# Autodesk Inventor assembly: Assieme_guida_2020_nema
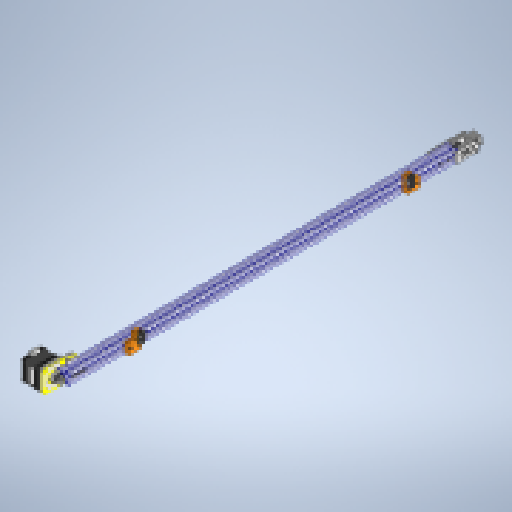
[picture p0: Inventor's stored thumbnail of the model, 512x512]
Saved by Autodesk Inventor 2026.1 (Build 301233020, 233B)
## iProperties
Created: 2026-01
Part Number: Assieme_guida_2020_nema
Document SubType Name: Assembly
Designer: hp
Sending System: Autodesk Inventor 2025
Preprocessor: ST-DEVELOPER v20
Title: Assieme_guida_2020_nema.stp
Author: R5800u
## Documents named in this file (16)
- C:\Users\hp\Documents\Inventor\DOM1_CartesianRobot\Assieme_guida_2020_nema - Copy.iam
- C:\Users\hp\Documents\Inventor\DOM1_CartesianRobot\2020 Belt Tensioner G_K.iam
- C:\Users\hp\Documents\Inventor\DOM1_CartesianRobot\GT2_20T.ipt
- C:\Users\hp\Documents\Inventor\DOM1_CartesianRobot\NO-NC Limit Switch.ipt
- C:\Users\hp\Documents\Inventor\DOM1_CartesianRobot\blocco_sensore.ipt
- C:\Users\hp\Documents\Inventor\DOM1_CartesianRobot\blocco_sensore_MIR.ipt
- C:\Users\hp\Documents\Inventor\DOM1_CartesianRobot\NEMA 42SHDC3030Z.ipt
- C:\Users\hp\Documents\Inventor\DOM1_CartesianRobot\blocco_nema.ipt
- C:\Users\hp\Documents\Inventor\DOM1_CartesianRobot\2020v2.ipt
- C:\Users\hp\Documents\Inventor\Content Center Files\R2026\en-US\ISO 4762(2)\ISO 4762 - M4 x 25ISO.ipt
- C:\Users\hp\Documents\Inventor\Content Center Files\R2026\en-US\ISO 4762(2)\ISO 4762 - M3 x 25ISO.ipt
- C:\Users\hp\Documents\Inventor\Content Center Files\R2021\en-US\ISO 4017(1)\ISO 4017 - M2 x 8 - ISO.ipt
- C:\Users\hp\Documents\Inventor\Content Center Files\R2026\en-US\ISO 4017(1)\ISO 4017 - M4 x 25 - ISO.ipt
- C:\Users\hp\Documents\Inventor\DOM1_CartesianRobot\2020 M4 (1).ipt
- C:\Users\hp\Documents\Inventor\Content Center Files\R2026\en-US\ANSI B18.3.1M(5)\ANSI B18.3.1M - M3x0.5 x 45(3).ipt
- C:\Users\hp\Documents\Inventor\Content Center Files\R2026\en-US\ISO 4032(2)\ISO 4032 - M3 - ISO.ipt
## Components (27 placed, 15 different names)
1. 2020:1
2. 2020 Belt Tensioner G_K:1 [sub-assembly]
3. GT2_20T:1 — Rigid:1
4. NO-NC Limit Switch:1 — Mate:9, Mate:10, Mate:11, Mate:36, Mate:37, Mate:38, Mate:39
5. NO-NC Limit Switch:2 — Mate:17, Mate:18, Mate:19
6. blocco_sensore:1
7. blocco_sensore_MIR:1 — Mate:15, Mate:16, Mate:17, Mate:18, Mate:19
8. NEMA 42SHDC3030Z:1
9. blocco_nema:1
10. ISO 4762 M3 x 25:1 — Mate:32, Mate:33
11. ISO 4762 M3 x 25:2 — Mate:34, Mate:35
12. ISO 4017 M2 x 8:1 — Mate:36, Mate:37
13. ISO 4017 M2 x 8:2 — Mate:38, Mate:39
14. ISO 4017 M4 x 25:1 — Mate:40, Mate:41
15. ISO 4017 M4 x 25:2 — Mate:42, Mate:43
16. 2020 M4 (1):1 — Mate:44, Angle:1, Mate:51
17. 2020 M4 (1):2 — Mate:45, Angle:2, Mate:50
18. ISO 4762 M4 x 25:1 — Mate:46, Mate:47, Mate:50
19. ISO 4762 M4 x 25:2 — Mate:48, Mate:49, Mate:51
20. Drilled Forged Hexagon Socket Head Cap Screw - 6 Holes - Metric M3x0.5 x 45:1 — Mate:52, Mate:53
21. ISO 4032 M3:1 — Mate:60, Mate:61
22. Drilled Forged Hexagon Socket Head Cap Screw - 6 Holes - Metric M3x0.5 x 45:2 — Mate:54, Mate:55
23. Drilled Forged Hexagon Socket Head Cap Screw - 6 Holes - Metric M3x0.5 x 45:3 — Mate:56, Mate:57
24. Drilled Forged Hexagon Socket Head Cap Screw - 6 Holes - Metric M3x0.5 x 45:4 — Mate:58, Mate:59
25. ISO 4032 M3:2 — Mate:62, Mate:63
26. ISO 4032 M3:3 — Mate:64, Mate:65
27. ISO 4032 M3:4 — Mate:66, Mate:67
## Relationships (47: Mate 44, Angle 2, WeldJoint 1)
- Rigid:1 [WeldJoint]: GT2_20T:1
- Mate:9: NO-NC Limit Switch:1
- Mate:10: NO-NC Limit Switch:1
- Mate:11: NO-NC Limit Switch:1
- Mate:15: blocco_sensore_MIR:1
- Mate:16: blocco_sensore_MIR:1
- Mate:17: NO-NC Limit Switch:2 ↔ blocco_sensore_MIR:1
- Mate:18: NO-NC Limit Switch:2 ↔ blocco_sensore_MIR:1
- Mate:19: NO-NC Limit Switch:2 ↔ blocco_sensore_MIR:1
- Mate:32: ISO 4762 M3 x 25:1
- Mate:33: ISO 4762 M3 x 25:1
- Mate:34: ISO 4762 M3 x 25:2
- Mate:35: ISO 4762 M3 x 25:2
- Mate:36: NO-NC Limit Switch:1 ↔ ISO 4017 M2 x 8:1
- Mate:37: NO-NC Limit Switch:1 ↔ ISO 4017 M2 x 8:1
- Mate:38: NO-NC Limit Switch:1 ↔ ISO 4017 M2 x 8:2
- Mate:39: NO-NC Limit Switch:1 ↔ ISO 4017 M2 x 8:2
- Mate:40: ISO 4017 M4 x 25:1
- Mate:41: ISO 4017 M4 x 25:1
- Mate:42: ISO 4017 M4 x 25:2
- Mate:43: ISO 4017 M4 x 25:2
- Mate:44: 2020 M4 (1):1
- Mate:45: 2020 M4 (1):2
- Angle:1: 2020 M4 (1):1
- Angle:2: 2020 M4 (1):2
- Mate:46: ISO 4762 M4 x 25:1
- Mate:47: ISO 4762 M4 x 25:1
- Mate:48: ISO 4762 M4 x 25:2
- Mate:49: ISO 4762 M4 x 25:2
- Mate:50: 2020 M4 (1):2 ↔ ISO 4762 M4 x 25:1
- Mate:51: 2020 M4 (1):1 ↔ ISO 4762 M4 x 25:2
- Mate:52: Drilled Forged Hexagon Socket Head Cap Screw - 6 Holes - Metric M3x0.5 x 45:1
- Mate:53: Drilled Forged Hexagon Socket Head Cap Screw - 6 Holes - Metric M3x0.5 x 45:1
- Mate:54: Drilled Forged Hexagon Socket Head Cap Screw - 6 Holes - Metric M3x0.5 x 45:2
- Mate:55: Drilled Forged Hexagon Socket Head Cap Screw - 6 Holes - Metric M3x0.5 x 45:2
- Mate:56: Drilled Forged Hexagon Socket Head Cap Screw - 6 Holes - Metric M3x0.5 x 45:3
- Mate:57: Drilled Forged Hexagon Socket Head Cap Screw - 6 Holes - Metric M3x0.5 x 45:3
- Mate:58: Drilled Forged Hexagon Socket Head Cap Screw - 6 Holes - Metric M3x0.5 x 45:4
- Mate:59: Drilled Forged Hexagon Socket Head Cap Screw - 6 Holes - Metric M3x0.5 x 45:4
- Mate:60: ISO 4032 M3:1
- Mate:61: ISO 4032 M3:1
- Mate:62: ISO 4032 M3:2
- Mate:63: ISO 4032 M3:2
- Mate:64: ISO 4032 M3:3
- Mate:65: ISO 4032 M3:3
- Mate:66: ISO 4032 M3:4
- Mate:67: ISO 4032 M3:4
